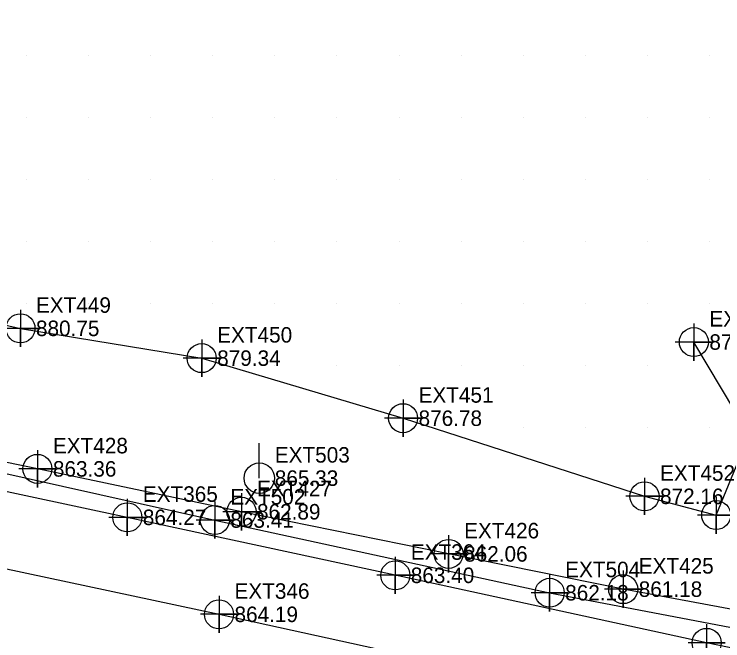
# Model space of a CAD drawing. Extents: x 1762120 to 1766775, y 709485 to 712965.
# Drawn here: x 1762528 to 1762642.2, y 712685.6 to 712786.6 of the extents above; entities that cross this region are included whole.
import ezdxf

# ---------------------------------------------------------------- set-up
doc = ezdxf.new("R2010")
doc.units = 0
for name, color, linetype in [('Exist DTM Breakline', 7, 'Continuous'), ('Exist DTM Breakline Cogo Elevation', 7, 'Continuous'), ('Exist DTM Breakline Cogo Number', 7, 'Continuous'), ('Exist DTM Breakline Cogo Point CELL', 7, 'Continuous'), ('Exist DTM Crownline', 7, 'Continuous'), ('Exist DTM Crownline Cogo Elevation', 7, 'Continuous'), ('Exist DTM Crownline Cogo Number', 7, 'Continuous'), ('Exist DTM Crownline Cogo Point CELL', 7, 'Continuous'), ('Exist DTM Drainline', 7, 'Continuous'), ('Exist DTM Drainline Cogo Elevation', 7, 'Continuous'), ('Exist DTM Drainline Cogo Number', 7, 'Continuous'), ('Exist DTM Drainline Cogo Point CELL', 7, 'Continuous'), ('Exist DTM QL2 LIDAR Elevation Point', 7, 'Continuous'), ('Exist Roads EOP', 7, 'Continuous'), ('Exist Roads EOP Cogo Elevation', 7, 'Continuous'), ('Exist Roads EOP Cogo Number', 7, 'Continuous'), ('Exist Roads EOP Cogo Point CELL', 7, 'Continuous'), ('Exist Utilities Gas UG Line SUE LOS C', 7, 'Continuous'), ('Exist Utilities Gas UG Line SUE LOS C Cogo Elevation', 7, 'Continuous'), ('Exist Utilities Gas UG Line SUE LOS C Cogo Number', 7, 'Continuous'), ('Exist Utilities Gas UG Line SUE LOS C Cogo Point CELL', 7, 'Continuous'), ('Exist Utilities Power Pole CELL', 7, 'Continuous'), ('Exist Utilities Power Pole Cogo Elevation', 7, 'Continuous'), ('Exist Utilities Power Pole Cogo Number', 7, 'Continuous')]:
    doc.layers.add(name, color=color, linetype=linetype)

msp = doc.modelspace()

# ---------------------------------------------------------------- linework, layer by layer
at = {"layer": 'Exist DTM Breakline'}
msp.add_lwpolyline([(1762269.75, 712786.47), (1762271.08, 712779.95), (1762292.95, 712778.9), (1762320.7, 712776.03), (1762354.47, 712776.48), (1762388.07, 712765.38), (1762412.81, 712762.42), (1762443.02, 712756.65), (1762473.16, 712749.14), (1762494.52, 712743.82), (1762529.01, 712735.95), (1762558.21, 712731.15), (1762590.65, 712721.47), (1762629.55, 712708.88), (1762641.1, 712705.86), (1762646.43, 712718.81), (1762637.5, 712733.74)], dxfattribs=at)
at = {"layer": 'Exist DTM Breakline Cogo Point CELL'}
for points in [[(1762529.01, 712738.95), (1762529.01, 712732.95), (1762529.01, 712735.95), (1762532.01, 712735.95), (1762526.01, 712735.95)], [(1762637.5, 712736.74), (1762637.5, 712730.74), (1762637.5, 712733.74), (1762640.5, 712733.74), (1762634.5, 712733.74)], [(1762558.21, 712734.15), (1762558.21, 712728.15), (1762558.21, 712731.15), (1762561.21, 712731.15), (1762555.21, 712731.15)], [(1762590.65, 712724.47), (1762590.65, 712718.47), (1762590.65, 712721.47), (1762593.65, 712721.47), (1762587.65, 712721.47)], [(1762629.55, 712711.88), (1762629.55, 712705.88), (1762629.55, 712708.88), (1762632.55, 712708.88), (1762626.55, 712708.88)], [(1762641.1, 712708.86), (1762641.1, 712702.86), (1762641.1, 712705.86), (1762644.1, 712705.86), (1762638.1, 712705.86)]]:
    msp.add_lwpolyline(points, dxfattribs=at)
for centre in [(1762529.01, 712735.95), (1762637.5, 712733.74), (1762558.21, 712731.15), (1762590.65, 712721.47), (1762629.55, 712708.88), (1762641.1, 712705.86)]:
    msp.add_circle(centre, 2.34, dxfattribs=at)
at = {"layer": 'Exist DTM Crownline'}
msp.add_lwpolyline([(1762166.55, 712774.69), (1762217.29, 712763.93), (1762266.93, 712753.16), (1762315.99, 712742.65), (1762361.3, 712733.13), (1762409.52, 712722.71), (1762461.51, 712711.51), (1762512.12, 712700.31), (1762561, 712689.86), (1762611.48, 712678.84), (1762663.77, 712667.96), (1762715.27, 712656.97), (1762767.73, 712645.75), (1762820.16, 712634.42), (1762873.56, 712623.12), (1762907.32, 712615.87), (1762954.84, 712607.61), (1762970.66, 712604.72)], dxfattribs=at)
at = {"layer": 'Exist DTM Crownline Cogo Point CELL'}
msp.add_lwpolyline([(1762561, 712692.86), (1762561, 712686.86), (1762561, 712689.86), (1762564, 712689.86), (1762558, 712689.86)], dxfattribs=at)
msp.add_circle((1762561, 712689.86), 2.34, dxfattribs=at)
at = {"layer": 'Exist DTM Drainline'}
msp.add_lwpolyline([(1762671.95, 712685.6), (1762648.35, 712689.78), (1762626.12, 712693.92), (1762597.99, 712699.6), (1762564.62, 712706.39), (1762531.74, 712713.3), (1762498.47, 712720.2), (1762464.8, 712728.4), (1762431.89, 712735.46), (1762397.08, 712742.59), (1762358.77, 712750.54), (1762329.32, 712757.66), (1762298.8, 712765.16), (1762269.77, 712772.56), (1762248.85, 712776.11)], dxfattribs=at)
at = {"layer": 'Exist DTM Drainline Cogo Point CELL'}
for points in [[(1762531.74, 712716.3), (1762531.74, 712710.3), (1762531.74, 712713.3), (1762534.74, 712713.3), (1762528.74, 712713.3)], [(1762564.62, 712709.39), (1762564.62, 712703.39), (1762564.62, 712706.39), (1762567.62, 712706.39), (1762561.62, 712706.39)], [(1762597.99, 712702.6), (1762597.99, 712696.6), (1762597.99, 712699.6), (1762600.99, 712699.6), (1762594.99, 712699.6)], [(1762626.12, 712696.92), (1762626.12, 712690.92), (1762626.12, 712693.92), (1762629.12, 712693.92), (1762623.12, 712693.92)]]:
    msp.add_lwpolyline(points, dxfattribs=at)
for centre in [(1762531.74, 712713.3), (1762564.62, 712706.39), (1762597.99, 712699.6), (1762626.12, 712693.92)]:
    msp.add_circle(centre, 2.34, dxfattribs=at)
at = {"layer": 'Exist DTM QL2 LIDAR Elevation Point'}
for p, q in [((1762530, 712780), (1762530, 712780)), ((1762540, 712780), (1762540, 712780)), ((1762550, 712780), (1762550, 712780)), ((1762560, 712780), (1762560, 712780)), ((1762570, 712780), (1762570, 712780)), ((1762580, 712780), (1762580, 712780)), ((1762590, 712780), (1762590, 712780)), ((1762600, 712780), (1762600, 712780)), ((1762610, 712780), (1762610, 712780)), ((1762620, 712780), (1762620, 712780)), ((1762630, 712780), (1762630, 712780)), ((1762640, 712780), (1762640, 712780)), ((1762530, 712770), (1762530, 712770)), ((1762540, 712770), (1762540, 712770)), ((1762550, 712770), (1762550, 712770)), ((1762560, 712770), (1762560, 712770)), ((1762570, 712770), (1762570, 712770)), ((1762580, 712770), (1762580, 712770)), ((1762590, 712770), (1762590, 712770)), ((1762600, 712770), (1762600, 712770)), ((1762610, 712770), (1762610, 712770)), ((1762620, 712770), (1762620, 712770)), ((1762630, 712770), (1762630, 712770)), ((1762640, 712770), (1762640, 712770)), ((1762530, 712760), (1762530, 712760)), ((1762540, 712760), (1762540, 712760)), ((1762550, 712760), (1762550, 712760)), ((1762560, 712760), (1762560, 712760)), ((1762570, 712760), (1762570, 712760)), ((1762580, 712760), (1762580, 712760)), ((1762590, 712760), (1762590, 712760)), ((1762600, 712760), (1762600, 712760)), ((1762610, 712760), (1762610, 712760)), ((1762620, 712760), (1762620, 712760)), ((1762630, 712760), (1762630, 712760)), ((1762640, 712760), (1762640, 712760)), ((1762530, 712750), (1762530, 712750)), ((1762540, 712750), (1762540, 712750)), ((1762550, 712750), (1762550, 712750)), ((1762560, 712750), (1762560, 712750)), ((1762570, 712750), (1762570, 712750)), ((1762580, 712750), (1762580, 712750)), ((1762590, 712750), (1762590, 712750)), ((1762600, 712750), (1762600, 712750)), ((1762610, 712750), (1762610, 712750)), ((1762620, 712750), (1762620, 712750)), ((1762630, 712750), (1762630, 712750)), ((1762640, 712750), (1762640, 712750)), ((1762530, 712740), (1762530, 712740)), ((1762540, 712740), (1762540, 712740)), ((1762550, 712740), (1762550, 712740)), ((1762560, 712740), (1762560, 712740)), ((1762570, 712740), (1762570, 712740)), ((1762580, 712740), (1762580, 712740)), ((1762590, 712740), (1762590, 712740)), ((1762600, 712740), (1762600, 712740)), ((1762610, 712740), (1762610, 712740)), ((1762620, 712740), (1762620, 712740)), ((1762630, 712740), (1762630, 712740)), ((1762640, 712740), (1762640, 712740)), ((1762570, 712730), (1762570, 712730)), ((1762580, 712730), (1762580, 712730)), ((1762590, 712730), (1762590, 712730)), ((1762600, 712730), (1762600, 712730)), ((1762610, 712730), (1762610, 712730)), ((1762620, 712730), (1762620, 712730)), ((1762630, 712730), (1762630, 712730)), ((1762610, 712720), (1762610, 712720)), ((1762620, 712720), (1762620, 712720)), ((1762630, 712720), (1762630, 712720)), ((1762640, 712720), (1762640, 712720)), ((1762640, 712710), (1762640, 712710))]:
    msp.add_line(p, q, dxfattribs=at)
at = {"layer": 'Exist Roads EOP'}
msp.add_lwpolyline([(1762972.64, 712616.33), (1762930.48, 712622.91), (1762881.99, 712633.2), (1762831.97, 712644.06), (1762782.82, 712654.41), (1762735.74, 712664.41), (1762686.68, 712675.53), (1762639.56, 712685.26), (1762589.4, 712696.15), (1762546.23, 712705.49), (1762496.4, 712716.08), (1762446.15, 712726.9), (1762396.23, 712737.69), (1762346.43, 712748.23), (1762295.97, 712759.18), (1762245.1, 712770.1), (1762193.68, 712780.97), (1762169, 712786.42)], dxfattribs=at)
at = {"layer": 'Exist Roads EOP Cogo Point CELL'}
for points in [[(1762546.23, 712708.49), (1762546.23, 712702.49), (1762546.23, 712705.49), (1762549.23, 712705.49), (1762543.23, 712705.49)], [(1762589.4, 712699.15), (1762589.4, 712693.15), (1762589.4, 712696.15), (1762592.4, 712696.15), (1762586.4, 712696.15)], [(1762639.56, 712688.26), (1762639.56, 712682.26), (1762639.56, 712685.26), (1762642.56, 712685.26), (1762636.56, 712685.26)]]:
    msp.add_lwpolyline(points, dxfattribs=at)
for centre in [(1762546.23, 712705.49), (1762589.4, 712696.15), (1762639.56, 712685.26)]:
    msp.add_circle(centre, 2.34, dxfattribs=at)
at = {"layer": 'Exist Utilities Gas UG Line SUE LOS C'}
msp.add_lwpolyline([(1762186.21, 712786.58), (1762241.95, 712774.53), (1762368.98, 712745.66), (1762446.66, 712730.32), (1762499.18, 712718.67), (1762560.33, 712705.06), (1762614.27, 712693.34), (1762654.57, 712685.66), (1762695.77, 712676.76), (1762747.57, 712665.85), (1762826.12, 712649.31), (1762887.98, 712636.74)], dxfattribs=at)
at = {"layer": 'Exist Utilities Gas UG Line SUE LOS C Cogo Point CELL'}
for points in [[(1762560.33, 712708.06), (1762560.33, 712702.06), (1762560.33, 712705.06), (1762563.33, 712705.06), (1762557.33, 712705.06)], [(1762614.27, 712696.34), (1762614.27, 712690.34), (1762614.27, 712693.34), (1762617.27, 712693.34), (1762611.27, 712693.34)]]:
    msp.add_lwpolyline(points, dxfattribs=at)
for centre in [(1762560.33, 712705.06), (1762614.27, 712693.34)]:
    msp.add_circle(centre, 2.34, dxfattribs=at)
at = {"layer": 'Exist Utilities Power Pole CELL'}
for q in [(1762567.49, 712717.43), (1762567.49, 712711.81)]:
    msp.add_line((1762567.49, 712711.81), q, dxfattribs=at)
msp.add_circle((1762567.49, 712711.81), 2.45, dxfattribs=at)

# ---------------------------------------------------------------- texts
at = {"layer": 'Exist DTM Breakline Cogo Elevation'}
for s, p in [('880.75', (1762531.51, 712734.7)), ('871.85', (1762640, 712732.49)), ('879.34', (1762560.71, 712729.9)), ('876.78', (1762593.15, 712720.22)), ('872.16', (1762632.05, 712707.63))]:
    msp.add_text(s, height=2.5, dxfattribs=at).set_placement(p)
at = {"layer": 'Exist DTM Breakline Cogo Number'}
for s, p in [('EXT449', (1762531.51, 712738.45)), ('EXT455', (1762640, 712736.24)), ('EXT450', (1762560.71, 712733.65)), ('EXT451', (1762593.15, 712723.97)), ('EXT452', (1762632.05, 712711.38))]:
    msp.add_text(s, height=2.5, dxfattribs=at).set_placement(p)
at = {"layer": 'Exist DTM Crownline Cogo Elevation'}
msp.add_text('864.19', height=2.5, dxfattribs=at).set_placement((1762563.5, 712688.61))
at = {"layer": 'Exist DTM Crownline Cogo Number'}
msp.add_text('EXT346', height=2.5, dxfattribs=at).set_placement((1762563.5, 712692.36))
at = {"layer": 'Exist DTM Drainline Cogo Elevation'}
for s, p in [('863.36', (1762534.24, 712712.05)), ('862.89', (1762567.12, 712705.14)), ('862.06', (1762600.49, 712698.35)), ('861.18', (1762628.62, 712692.67))]:
    msp.add_text(s, height=2.5, dxfattribs=at).set_placement(p)
at = {"layer": 'Exist DTM Drainline Cogo Number'}
for s, p in [('EXT428', (1762534.24, 712715.8)), ('EXT427', (1762567.12, 712708.89)), ('EXT426', (1762600.49, 712702.1)), ('EXT425', (1762628.62, 712696.42))]:
    msp.add_text(s, height=2.5, dxfattribs=at).set_placement(p)
at = {"layer": 'Exist Roads EOP Cogo Elevation'}
for s, p in [('864.27', (1762548.73, 712704.24)), ('863.40', (1762591.9, 712694.9))]:
    msp.add_text(s, height=2.5, dxfattribs=at).set_placement(p)
at = {"layer": 'Exist Roads EOP Cogo Number'}
for s, p in [('EXT365', (1762548.73, 712707.99)), ('EXT364', (1762591.9, 712698.65))]:
    msp.add_text(s, height=2.5, dxfattribs=at).set_placement(p)
at = {"layer": 'Exist Utilities Gas UG Line SUE LOS C Cogo Elevation'}
for s, p in [('863.41', (1762562.83, 712703.81)), ('862.18', (1762616.77, 712692.09))]:
    msp.add_text(s, height=2.5, dxfattribs=at).set_placement(p)
at = {"layer": 'Exist Utilities Gas UG Line SUE LOS C Cogo Number'}
for s, p in [('EXT502', (1762562.83, 712707.56)), ('EXT504', (1762616.77, 712695.84))]:
    msp.add_text(s, height=2.5, dxfattribs=at).set_placement(p)
at = {"layer": 'Exist Utilities Power Pole Cogo Elevation'}
msp.add_text('865.33', height=2.5, dxfattribs=at).set_placement((1762569.99, 712710.56))
at = {"layer": 'Exist Utilities Power Pole Cogo Number'}
msp.add_text('EXT503', height=2.5, dxfattribs=at).set_placement((1762569.99, 712714.31))

doc.saveas('drawing.dxf')
